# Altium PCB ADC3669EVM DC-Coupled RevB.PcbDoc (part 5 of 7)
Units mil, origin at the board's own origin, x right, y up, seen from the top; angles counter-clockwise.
Board outline 5000 x 2716.54 mil, 12 copper layers (Top Layer, L2 GND, L3 SIG, L4 GND, L5 PWR, L6 GND, L7 GND, L8 PWR, L9 GND, L10 PWR, L11 GND, Bottom Layer), stack 61 mil thick; 546 components, 341 nets, 2088 pads, 1256 vias.
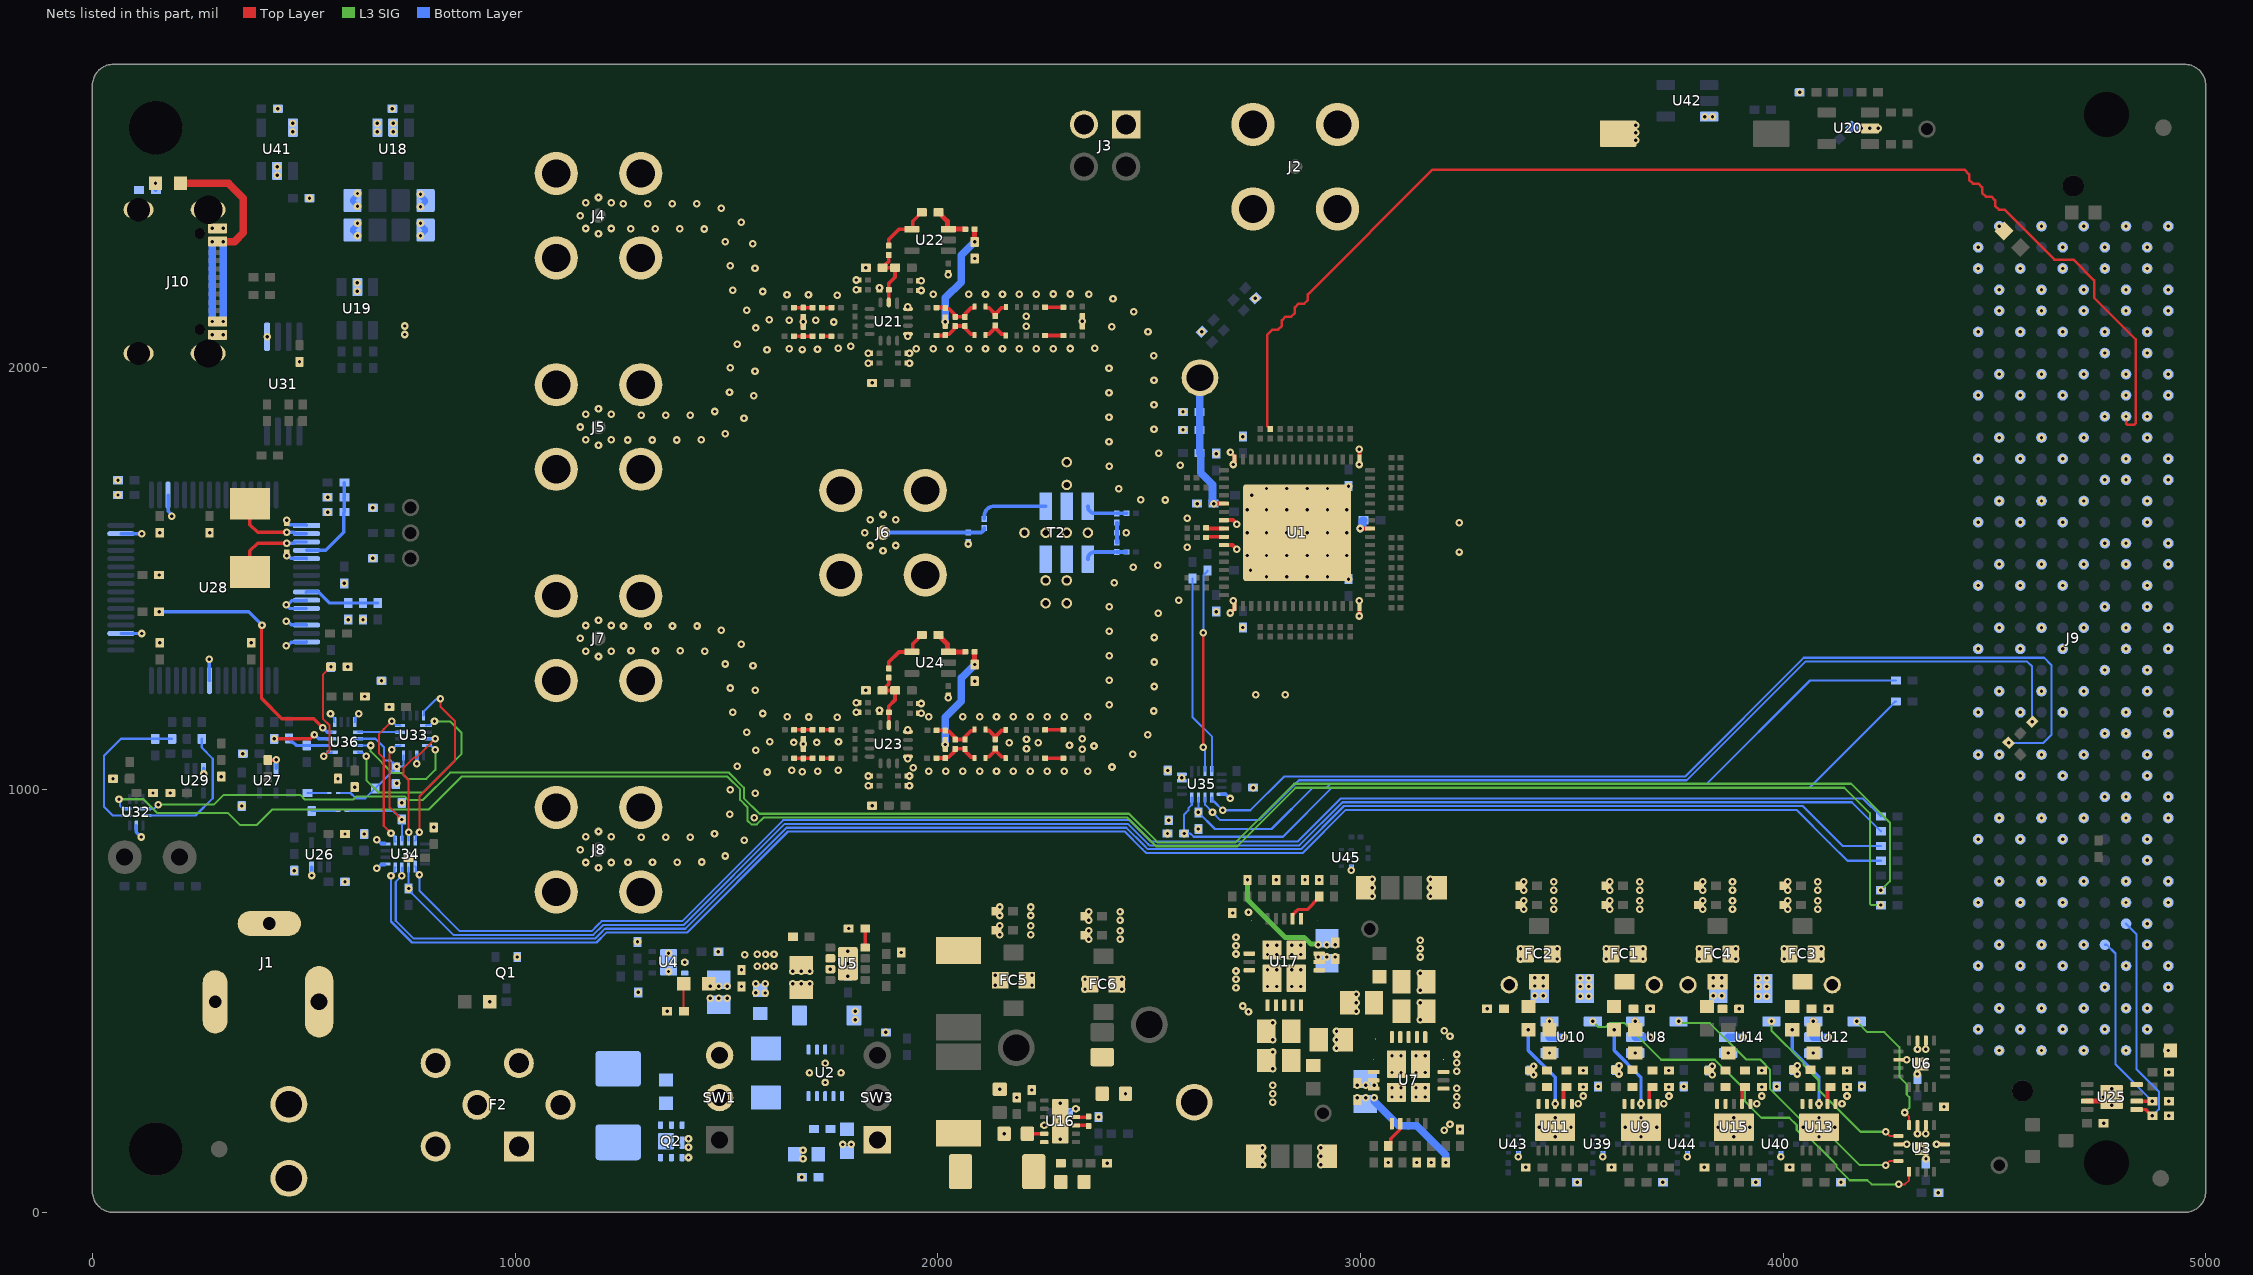
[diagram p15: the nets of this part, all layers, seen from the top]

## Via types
v1: diameter 18, hole 8, Top Layer to Bottom Layer, tented both sides, 1256 vias

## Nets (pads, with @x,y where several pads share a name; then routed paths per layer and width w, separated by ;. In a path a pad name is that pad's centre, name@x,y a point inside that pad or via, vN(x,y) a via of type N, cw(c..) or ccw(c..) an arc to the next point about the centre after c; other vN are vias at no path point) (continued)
FMC_DOUT15_p: J9.C10 R119.2 | length 2919.6
  Top Layer w6: R119.2@2786.79,1853.55 2786.79,1854.33 2783.49,1857.63 2782.96,1857.63 2779.45,1861.15 2779.45,2075.63 2792.38,2088.56 2805.55,2088.56 2814.35,2097.36 2814.35,2110.54 2823.15,2119.34 2836.33,2119.34 2845.13,2128.14 2845.13,2141.31 2853.93,2150.11 2867.1,2150.11 2875.9,2158.92 2875.9,2172.09 3170.82,2467 4429,2467 4440.08,2455.92 4440.08,2442.74 4448.89,2433.94 4462.06,2433.94 4470.86,2425.14 4470.86,2411.97 4479.66,2403.16 4492.84,2403.16 4501.64,2394.36 4501.64,2381.19 4510.44,2372.39 4523.61,2372.39 4641.93,2254.07 4686.72,2254.07 4735.87,2204.92 4735.87,2164.1 4834,2065.97 4834,1866.78 4830.49,1863.27 4814.93,1863.27 4811.42,1866.78 v1(4811.42,1883.27)
FMC_I2C_SCL: R180.1 U32.1 | length 4527.1
  L3 SIG w5: v1(155.65,964.87) 287.52,964.87 310.51,987.86 491.7,987.86 502.7,976.86 616.93,976.86 624.5,984.43 738.73,984.43 747.49,975.68 781.68,975.68 846.47,1040.46 1506.18,1040.46 1541.45,1005.19 1541.45,980.28 1578.32,943.41 2452.43,943.41 2520.3,875.54 2704.8,875.54 2843.47,1014.21 4161.02,1014.21 4252.68,922.54 4252.68,783.37 v1(4231.31,762)
  Bottom Layer w5: U32.1@125.65,954.87 145.65,954.87 v1(155.65,964.87) ; R180.1@4230.91,761.6 v1(4231.31,762)
FMC_I2C_SDA: R181.1 U32.7 | length 4688.5
  L3 SIG w5: v1(62.99,977.49) 121.12,977.49 153.93,944.68 321.2,944.68 349.59,916.29 388.18,916.29 425.33,953.43 795.71,953.43 873.73,1031.46 1502.45,1031.46 1532.45,1001.47 1532.45,976.55 1550.06,958.94 1550.06,927.13 1559.14,918.06 1571.98,918.06 1588.33,934.41 2448.7,934.41 2516.57,866.54 2708.53,866.54 2846.75,1004.76 4145.04,1004.76 4205.43,944.37 4205.43,730.47 4208.35,727.54 v1(4230.78,727.54)
  Bottom Layer w5: v1(62.99,977.49) 65.48,975 65.48,961.9 72.5,954.87 U32.7@80.38,954.87 ; v1(4230.78,727.54) R181.1@4231.31,727
FMC_RESET: R193.1 U34.4 | length 3899.5
  Bottom Layer w5: U34.4@716.56,816.57 715.13,815.13 715.13,806 706.56,797.44 v1(706.56,796.57) 706.56,688.51 756.35,638.73 1192.73,638.73 1216.14,662.14 1406.69,662.14 1645.82,901.27 2442.44,901.27 2484.21,859.49 2493.21,850.49 2863.47,850.49 2965.49,952.51 4031.86,952.51 4110.56,873.81 ; 4110.58,873.81 4152.39,832 R193.1@4231.31,832
FMC_RESET_1p8V: U33.12 U34.9 | length 337.3
  Top Layer w5: v1(706.56,897.59) 689.47,914.69 689.47,1074.79 677.87,1086.39 677.87,1131.63 689.47,1143.22 v1(708.37,1162.13)
  Bottom Layer w5: v1(706.56,897.59) 706.56,896.73 715.13,888.17 715.13,879.03 U34.9@716.56,877.59 ; v1(708.37,1162.13) 709.24,1162.13 717.8,1153.56 726.94,1153.56 U33.12@728.37,1152.13
FMC_SCLK: R200.1 U34.1 | length 3748.3
  Bottom Layer w5: U34.1@763.81,818.54 765.24,817.1 765.24,807.97 773.81,799.41 v1(773.81,798.54) 773.81,760.92 869,665.73 1181.54,665.73 1195.95,680.14 1204.96,689.14 1395.5,689.14 1634.63,928.27 2453.62,928.27 2504.4,877.49 2851.87,877.49 2953.89,979.51 4188.8,979.51 R200.1@4231.31,937
FMC_SCLK_1p8V: U33.16 U34.12 | length 451.4
  Top Layer w5: v1(773.81,899.56) 773.81,984.42 858,1068.61 858,1162 823.49,1196.51 v1(823.49,1215.75)
  Bottom Layer w5: U34.12@763.81,879.56 765.24,881 765.24,890.13 773.81,898.7 v1(773.81,899.56) ; U33.16@783.49,1175.75 784.93,1177.18 784.93,1186.32 812.26,1213.65 821.39,1213.65 v1(823.49,1215.75)
FMC_SDI_1p8V: NT2.1 R208.2 | length 55.5
  Bottom Layer w5: R208.2@518.83,949.74 NT2.1@574.33,949.74
FMC_SDIO_1p8V: NT2.2 R259.1 U33.9 U34.10 | length 376
  Top Layer w5: v1(708.37,1094.88) 708.37,1091.36 703.35,1086.34 703.35,958.53 v1(732.31,929.56)
  Bottom Layer w5: NT2.2@609.33,949.74 712.13,949.74 723,938.87 724.97,938.87 732.31,931.53 v1(732.31,929.56) ; v1(708.37,1094.88) 709.24,1094.88 717.8,1103.44 726.94,1103.44 U33.9@728.37,1104.88 ; U34.10@732.31,879.56 R259.1@732.31,919.56
FMC_SDO: R204.1 U34.3 | length 3874.8
  Bottom Layer w5: U34.3@732.31,816.57 v1(732.31,796.57) 717.8,782.06 717.8,690 760.08,647.73 1189,647.73 1203.41,662.14 1212.41,671.14 1402.96,671.14 1642.09,910.27 2446.16,910.27 2487.94,868.49 2496.94,859.49 2859.33,859.49 2961.35,961.51 4046.38,961.51 4140.89,867 R204.1@4231.31,867
FMC_SEN: R196.1 R199.1 U34.2 | length 3771.5
  Bottom Layer w5: v1(748.06,766.57) 755.4,759.23 755.4,755.33 854,656.73 1185.27,656.73 1208.68,680.14 1399.23,680.14 1638.36,919.27 2449.89,919.27 2498.05,871.12 2500.67,868.49 2855.6,868.49 2957.62,970.51 4162.8,970.51 R199.1@4231.31,902 ; R196.1@748.06,776.57 U34.2@748.06,816.57
FMC_SEN_1p8V: U33.3 U34.11 | length 300.5
  Top Layer w5: v1(748.06,899.56) 748.06,1023.28 736.5,1034.84 736.5,1051.93 761.32,1076.76 767.5,1076.76 v1(811.37,1120.63)
  Bottom Layer w5: U34.11@748.06,879.56 v1(748.06,899.56) ; U33.3@791.37,1120.63 v1(811.37,1120.63)
FTDI_I2C_SCL: R218.2 U32.2 | length 325.5
  Bottom Layer w5: U32.2@127.62,939.13 243.87,939.13 284.7,979.95 284.7,1073.84 258.64,1099.89 R218.2@258.64,1120.63
FTDI_I2C_SDA: R220.2 R221.2 U32.6 | length 360
  Bottom Layer w5: U32.6@80.38,939.13 47.96,939.13 27.5,959.59 27.5,1080.5 67.63,1120.63 R221.2@148.64,1120.63 R220.2@188.64,1120.63
FTDI_RESET: R222.2 U36.4 | length 628.5
  Top Layer w8: v1(401.42,1389.39) 400.19,1388.16 400.19,1216 448.38,1167.81 523.95,1167.81 v1(545.38,1146.38)
  Bottom Layer w8: v1(158.14,1421.08) 369.74,1421.08 v1(401.42,1389.39) ; v1(545.38,1146.38) 555.38,1136.38 U36.4@565.38,1136.38
FTDI_RESET_1p8V: U33.11 U36.9 | length 100
  Bottom Layer w5: U36.9@628.37,1136.38 U33.11@728.37,1136.38
FTDI_SCLK: R212.2 R216.2 U36.1 | length 255.9
  Top Layer w5: v1(547.35,1079.13) 560.88,1092.67 560.88,1152.8 545.38,1168.3 545.38,1271.92 v1(564.43,1290.97)
  Bottom Layer w5: v1(547.35,1079.13) 548.22,1079.13 556.78,1087.7 565.91,1087.7 U36.1@567.35,1089.13
FTDI_SCLK_1p8V: U33.1 U36.12 | length 504.8
  L3 SIG w5: v1(648.37,1079.13) 648.37,1022.59 677.39,993.57 781.67,993.57 873.73,1085.63 873.73,1134.26 846.47,1161.53 810,1161.53 v1(809.4,1162.13)
  Bottom Layer w5: U36.12@628.37,1089.13 629.81,1087.7 638.95,1087.7 647.51,1079.13 v1(648.37,1079.13) ; U33.1@789.4,1152.13 790.84,1153.56 799.97,1153.56 808.53,1162.13 v1(809.4,1162.13)
FTDI_SDI_1p8V: NT1.1 R211.2 | length 44.5
  Bottom Layer w5: R211.2@509.12,992.36 NT1.1@553.66,992.36
FTDI_SDIO_1p8V: NT1.2 R188.2 R266.1 U33.8 U36.10 | length 345.7
  Bottom Layer w5: NT1.2@588.66,992.36 610.64,992.36 623.05,979.95 645.97,979.95 711.7,1045.69 712.66,1045.69 720,1053.03 720,1056.97 712.66,1064.31 710.69,1064.31 706.11,1068.89 692.93,1068.89 690,1071.82 690,1100.46 669.83,1120.63 U36.10@628.37,1120.63 ; R266.1@720,1055.54 733.32,1055.54 736.25,1058.47 U33.8@736.25,1081.26
  other v1: 720,1055
FTDI_SDO: R214.2 U36.3 | length 143.3
  Top Layer w8: v1(430.38,1120.63) 515.38,1120.63 v1(525.38,1130.63)
  Bottom Layer w8: v1(525.38,1130.63) 535.38,1120.63 U36.3@565.38,1120.63
FTDI_SEN: R209.1 R213.2 U36.2 | length 108.1
  Bottom Layer w8: R213.2@465.38,1121.61 465.38,1119.65 471.22,1113.8 473.19,1113.8 482.11,1104.88 U36.2@565.38,1104.88
FTDI_SEN_1p8V: U33.4 U36.11 | length 304.6
  L3 SIG w5: v1(658.37,1104.88) 658.37,1091.05 709.93,1039.5 731.84,1039.5 745.58,1025.76 789.91,1025.76 811.37,1047.21 v1(811.37,1094.88)
  Bottom Layer w5: U36.11@628.37,1104.88 v1(658.37,1104.88) ; U33.4@791.37,1104.88 792.8,1103.44 801.94,1103.44 810.5,1094.88 v1(811.37,1094.88)
GA0_FMC: J9.C34 R185.2 U25.1 | length 537.6
  Top Layer w8: U25.1@4836.47,243.61 4858.47,243.61 4865.66,236.42 4865.66,234.45 4871.5,228.61 v1(4873.47,228.61)
  Bottom Layer w5: J9.C34@4811.42,683.27 4836.12,658.56 4836.12,338.89 4888.97,286.04 4888.97,244.11 v1(4873.47,228.61)
GA1_FMC: J9.D35 R186.2 U25.2 | length 455.8
  Top Layer w8: U25.2@4836.47,263.3 v1(4873.47,263.3)
  Bottom Layer w5: J9.D35@4761.42,633.27 4765.59,633.27 4786.34,612.52 4786.34,350.43 v1(4873.47,263.3)
GND: C1.1 C3.1 C4.1 C5.1 C6.1 C7.1 C8.1 C9.1 C10.1 C11.1 C12.1 C13.1 C14.1 C15.1 C16.1 C17.1 C18.1 C19.1 C20.1 C21.1 C22.1 C23.1 C24.1 C25.1 C26.1 C27.1 C28.1 C29.1 C30.1 C31.1 C32.1 C33.1 C34.1 C35.1 C36.1 C37.1 C38.1 C39.1 C40.1 C41.1 C42.1 C43.1 C44.1 C45.1 C46.1 C47.1 C48.1 C49.1 C50.1 C51.1 C53.1 C54.1 C55.1 C56.1 C57.1 C58.1 C59.1 C60.1 C61.1 C62.1 C63.1 C64.1 C65.1 C66.1 C67.1 C71.1 C72.1 C77.1 C78.1 C80.1 C81.1 C82.1 C83.1 C84.1 C85.1 C86.1 C87.1 C88.1 C89.1 C90.1 C96.1 C99.2 C109.1 C115.1 C118.2 C122.1 C123.1 C124.1 C126.1 C127.1 C128.1 C129.1 C130.1 C131.1 C132.1 C133.1 C135.1 C138.2 C140.1 C142.2 C144.1 C145.1 C146.1 C147.1 C148.1 C149.1 C150.1 C151.1 C152.1 C154.1 C157.2 C159.2 C161.2 C163.1 C164.1 C165.1 C166.1 C167.1 C168.1 C169.1 C170.1 C171.1 C172.1 C173.1 C174.1 C175.1 C176.1 C177.1 C178.1 C180.1 C181.1 C182.1 C183.1 C184.1 C185.1 C186.2 C187.2 C188.2 C189.1 C190.2 D4.2 FC1.2 FC2.2 FC3.2 FC4.2 FC5.2 FC6.2 J2.2 J2.3 J2.4 J2.5 J3.1 J3.3 J4.2 J4.3 J4.4 J4.5 J5.2 J5.3 J5.4 J5.5 J6.2 J6.3 J6.4 J6.5 J7.2 J7.3 J7.4 J7.5 J8.2 J8.3 J8.4 J8.5 J9.A1 J9.A4 J9.A5 J9.A8 J9.A9 J9.A12 J9.A13 J9.A16 J9.A17 J9.A20 J9.A21 J9.A24 J9.A25 J9.A28 J9.A29 J9.A32 J9.A33 J9.A36 J9.A37 J9.A40 J9.B2 J9.B3 J9.B6 J9.B7 J9.B10 J9.B11 J9.B14 J9.B15 J9.B18 J9.B19 J9.B22 J9.B23 J9.B26 J9.B27 J9.B30 J9.B31 J9.B34 J9.B35 J9.B38 J9.B39 J9.C1 J9.C4 J9.C5 J9.C8 J9.C9 J9.C12 J9.C13 J9.C16 J9.C17 J9.C20 J9.C21 J9.C24 J9.C25 J9.C28 J9.C29 J9.C32 J9.C33 J9.C36 J9.C38 J9.C40 J9.D2 J9.D3 J9.D6 J9.D7 J9.D10 J9.D13 J9.D16 J9.D19 J9.D22 J9.D25 J9.D28 J9.D37 J9.D39 J9.E1 J9.E4 J9.E5 J9.E8 J9.E11 J9.E14 J9.E17 J9.E20 J9.E23 J9.E26 J9.E29 J9.E32 J9.E35 J9.E38 J9.E40 J9.F2 J9.F3 J9.F6 J9.F9 J9.F12 J9.F15 J9.F18 J9.F21 J9.F24 J9.F27 J9.F30 J9.F33 J9.F36 J9.F39 J9.G1 J9.G4 J9.G5 J9.G8 J9.G11 J9.G14 J9.G17 J9.G20 J9.G23 J9.G26 J9.G29 J9.G32 J9.G35 J9.G38 J9.G40 J9.H3 J9.H6 J9.H9 J9.H12 J9.H15 J9.H18 J9.H21 J9.H24 J9.H27 J9.H30 J9.H33 J9.H36 J9.H39 J9.J1 J9.J4 J9.J5 J9.J8 J9.J11 J9.J14 J9.J17 J9.J20 J9.J23 J9.J26 J9.J29 J9.J32 J9.J35 J9.J38 J9.J40 J9.K2 J9.K3 J9.K6 J9.K9 J9.K12 J9.K15 J9.K18 J9.K21 J9.K24 J9.K26 J9.K30 J9.K33 J9.K36 J9.K39 J10.1 J10.2 J10.3 J10.4 J10.A1 J10.B1 Q1.2 Q2.4 Q2.7 R3.1 R4.1 R5.1 R11.1 R12.1 R15.1 R17.1 R18.1 R24.1 R26.1 R27.1 R33.1 R34.1 R35.1 R41.1 R43.1 R44.1 R50.1 R51.1 R52.1 R56.1 R57.1 R58.1 R67.1 R69.1 R70.1 R75.1 R78.1 R80.1 R122.2 R123.2 R134.1 R144.1 R146.1 R152.1 R157.1 R163.1 R165.2 R171.1 R176.1 R179.1 R182.1 R185.1 R186.1 R187.1 R190.1 R192.1 R207.1 R210.1 R216.1 R225.1 R240.1 R248.1 R251.1 R252.1 R253.1 R256.1 R259.2 R260.1 R261.1 R262.1 R263.1 R266.2 R267.1 SW2.2 SW3.3 T2.1 T2.2 T2.5 TP2.1 U1.1 U1.16 U1.23 U1.26 U1.33 U1.48 U1.57 U1.65@2732.56,1554.33 U1.65@2732.56,1608.27 U1.65@2732.56,1662.21 U1.65@2777.95,1503.78 U1.65@2777.95,1554.33 U1.65@2777.95,1608.27 U1.65@2777.95,1662.21 U1.65@2777.95,1712.76 U1.65@2825.99,1503.78 U1.65@2825.99,1554.33 U1.65@2825.99,1608.27 U1.65@2825.99,1662.21 U1.65@2825.99,1712.76 U1.65@2850,1608.27 U1.65@2874.02,1503.78 U1.65@2874.02,1554.33 U1.65@2874.02,1608.27 U1.65@2874.02,1662.21 U1.65@2874.02,1712.76 U1.65@2922.05,1503.78 U1.65@2922.05,1554.33 U1.65@2922.05,1608.27 U1.65@2922.05,1662.21 U1.65@2922.05,1712.76 U1.65@2967.44,1554.33 U1.65@2967.44,1608.27 U1.65@2967.44,1662.21 U2.11 U3.2 U3.3 U3.6 U3.15 U3.17 U4.5 U4.7@1363.17,569.93 U4.7@1363.17,591.58 U4.7@1363.17,613.23 U5.3 U5.9 U6.2 U6.3 U6.6 U6.17 U7.1 U7.2 U7.3 U7.5 U7.6 U7.7 U7.8 U7.9 U7.16 U7.17 U7.20 U7.25 U7.26 U7.28 U8.2 U9.6 U9.11 U10.2 U11.6 U11.11 U12.2 U13.6 U13.11 U14.2 U15.6 U15.11 U16.4 U16.13 U17.1 U17.2 U17.3 U17.5 U17.6 U17.7 U17.8 U17.9 U17.16 U17.17 U17.20 U17.25 U17.26 U17.28 U18.2 U19.2 U20.2 U21.11 U21.14 U23.11 U23.14 U25.4 U25.7 U25.9 U26.3 U27.3 U28.1 U28.5 U28.10 U28.11 U28.13 U28.15 U28.25 U28.35 U28.47 U28.51 U29.3 U31.5 U32.4 U33.6 U34.5 U34.8 U35.8 U35.15 U35.16 U36.5 U36.8 U39.3 U40.3 U41.2 U42.3 U43.3 U44.3 U45.3 | length 1746.8
  Top Layer w8: C173.1@415.07,1070 415.38,1070.31 434.44,1070.31 v1(434.75,1070.63) ; U3.6@4272.68,161.29 v1(4292.68,161.29) ; U6.6@4272.68,361.29 v1(4292.69,361.28) ; v1(4317.96,386.56) U6.3@4317.96,406.56 ; v1(4337.64,186.56) U3.2@4337.64,206.56 ; v1(4337.65,386.56) U6.2@4337.64,406.56 ; v1(4362.92,161.29) U3.15@4382.92,161.29
  Top Layer w9.5: U1.26@2670.95,1578.83 U1.26@2676.86,1578.83 ; U1.26@2676.6,1578.57 U1.26@2676.77,1578.74 U1.26@2676.86,1578.83 ; U1.23@2683.19,1637.8 2698.03,1637.8 v1(2707.84,1628.05) v1(2707.84,1628.05) ; 2688.67,1578.83 U1.26@2682.76,1578.83 ; v1(2692.36,1418.14) 2702.19,1427.96 2702.19,1434.87 U1.33@2702.36,1435.04 U1.33@2702.36,1446.85 ; v1(2692.53,1798.23) 2702.36,1788.4 U1.16@2702.36,1781.5 2702.53,1781.33 v1@2702.53,1769.52 ; v1(2707.67,1568.83) 2707.6,1568.83 2697.85,1578.57 2683.02,1578.57 U1.26@2682.76,1578.83 ; v1(2997.64,1411.23) U1.48@2997.64,1435.04 v1(2997.64,1446.85) ; v1(2997.64,1769.69) U1.1@2997.64,1781.5 v1(2997.64,1805.31) ; v1(2999.42,1618.11) U1.57@3023.23,1618.11 ; U1.26@2676.86,1578.83 U1.26@2682.76,1578.83
  Top Layer w12: R144.1@1681.83,2095.24 R146.1@1681.83,2118.54 ; R163.1@1682.22,1096.62 R165.2@1682.22,1119.92 ; v1(1807.52,1183.12) C151.1@1812.52,1183.12 ; v1(1807.52,1206.12) C149.1@1812.52,1206.12 ; v1(1807.52,2183.12) C131.1@1812.52,2183.12 ; v1(1807.52,2206.12) C133.1@1812.52,2206.12 ; v1(1835.35,1009.56) C152.1@1840.35,1009.56 ; v1(1835.35,1032.56) C150.1@1840.35,1032.56 ; v1(1835.35,2009.56) C130.1@1840.35,2009.56 ; v1(1835.35,2032.56) C132.1@1840.35,2032.56 ; C159.2@1862.2,1183.12 v1(1862.2,1188.12) ; C140.1@1862.2,2183.12 v1(1862.2,2188.12) ; C148.1@1928.15,1009.56 v1(1933.15,1009.56) ; C145.1@1928.15,1032.56 v1(1933.15,1032.56) ; C128.1@1928.15,2009.56 v1(1933.15,2009.56) ; C127.1@1928.15,2032.56 v1(1933.15,2032.56) ; v1(1929.53,1073.31) U23.11@1929.53,1078.31 ; U23.14@1929.53,1137.37 v1(1929.53,1142.37) ; v1(1929.53,2073.31) U21.11@1929.53,2078.31 ; U21.14@1929.53,2137.37 v1(1929.53,2142.37) ; C146.1@1955.98,1181.15 v1(1960.98,1181.15) ; C147.1@1955.98,1204.15 v1(1960.98,1204.15) ; C126.1@1955.98,2181.15 v1(1960.98,2181.15) ; C129.1@1955.98,2204.15 v1(1960.98,2204.15) ; v1(2025.23,1218.07) C163.1@2025.23,1223.07 ; v1(2025.23,2218.07) C144.1@2025.23,2223.07 ; U25.7@4719.22,263.3 4777.42,263.3 U25.9@4777.42,273.14
  Bottom Layer w5: v1(563.26,1180) 563.26,1179.13 571.82,1170.57 571.82,1161.44 U36.5@573.26,1160 ; U36.8@620.5,1160 621.94,1161.44 621.94,1170.57 630.5,1179.13 v1(630.5,1180)
  Bottom Layer w8: U28.35@67.63,1369.71 v1(116.5,1369.71) ; U28.47@67.63,1605.93 v1(116.8,1605.93) ; U32.4@104,915.5 104,899.99 v1(115.82,888.17) ; U28.51@178.85,1697.47 179.58,1696.74 179.58,1658.51 187.91,1650.17 v1(187.91,1647.47) ; U29.3@263.01,1050.63 263.42,1050.22 v1(263.42,1037.44) ; v1(276.64,1308.49) 276.96,1308.17 276.96,1258.8 U28.25@277.27,1258.49 ; U27.3@434.75,1050.63 v1(434.75,1070.63) ; v1(459.06,1340.52) 461.77,1340.52 469.11,1347.86 ; v1(459.06,1398.9) 461.77,1398.9 469.11,1391.56 ; v1(459.45,1638.06) 459.45,1635.36 466.05,1628.76 466.05,1627.03 505.19,1627.03 U28.1@506.6,1625.62 ; v1(459.92,1554.11) 462.63,1554.11 469.14,1547.6 505.87,1547.6 U28.5@506.6,1546.88 ; 469.14,1347.86 470.57,1349.3 505.87,1349.3 U28.15@506.6,1350.02 ; 469.14,1391.56 470.57,1390.12 505.87,1390.12 U28.13@506.6,1389.39 ; U28.11@506.6,1428.77 468.46,1428.77 v1(459.06,1438.17) 461.77,1438.17 471.32,1447.72 505.87,1447.72 U28.10@506.6,1448.45 ; v1(518.83,797.1) U26.3@518.83,817.1 ; v1(672.94,814.44) 673.81,814.44 682.37,823.01 U34.5@691.5,823.01 ; v1(672.94,881.69) 673.81,881.69 682.37,873.13 U34.8@691.5,873.13 ; v1(767.74,1061.26) U33.6@767.74,1081.26 ; U35.8@2671.9,989.51 2681.9,989.51 v1(2691.9,979.51) ; v1(2978.59,809.7) U45.3@2978.59,819.7 ; v1(3373.64,131.6) U43.3@3373.64,141.6 ; v1(3573.64,131.6) U39.3@3573.64,141.6 ; v1(3773.64,131.6) U44.3@3773.64,141.6 ; v1(3994.95,131.6) U40.3@3994.95,141.6
  Bottom Layer w12: v1(627.29,2310.67) 615.29,2322.67 615.29,2325.67 627.29,2337.67 v1(627.29,2340.67) ; v1(627.29,2380.67) 615.29,2392.67 615.29,2395.67 627.29,2407.67 v1(627.29,2410.67) ; v1(776.4,2310.67) 788.4,2322.67 788.4,2325.67 776.4,2337.67 v1(776.4,2340.67) ; v1(776.4,2379.17) 788.4,2391.17 C67.1@788.4,2394.17 776.4,2406.17 v1(776.4,2409.17)
  Bottom Layer w18: v1(2999.42,1618.11) 3004.86,1623.55 3004.86,1636.95 3005.7,1637.8 C89.1@3007.67,1637.8 ; U10.2@3447.46,414.63 v1(3482.46,414.63) ; U8.2@3650.39,414.63 v1(3685.39,414.63) ; U14.2@3870.14,414.63 v1(3905.14,414.63) ; U12.2@4071.7,414.63 v1(4106.7,414.63) ; C90.1@4161.27,2567.84 4162.66,2569.23 4163.85,2569.23 4165.24,2567.84 4182.64,2567.84 v1(4185.47,2565)
  other v1: 4367.17,46.52 3512.81,71.52 3715.74,71.52 3935.5,71.52 4137.05,71.52 1678.63,83 3391.19,106.52 3594.12,106.52 3813.87,106.52 4015.43,106.52 2768.31,112.92 2905.79,112.92 2400.89,116.54 3065.64,118.06 3133.64,118.06 3167.64,118.06 1681.27,127.4 4338.16,127.51 1410.41,130.01 2768.31,132.92 2905.79,132.92 1681.27,147.4 2768.31,152.92 2905.79,152.92 1410.41,154.65 1775.71,160.92 1795.71,160.92 1410.41,174.65 2157.03,186.23 4317.96,186.56 3198.26,194.89 3235.64,196.8 2252.15,205.91 3211.98,208.61 4758.59,211.18 2380.54,225.88 4912.84,228.61 4380.59,250.04 3228.02,253.79 3515.17,256.76 3718.1,256.76 3937.86,256.76 4139.41,256.76 2792.37,260.81 4912.84,263.3 2187.15,271.86 3228.02,273.79 3527.06,275.54 3729.98,275.54 3949.74,275.54 4151.29,275.54 2444.25,280.81 2792.37,280.81 2222.15,289.65 2146.65,291.54 3228.02,293.79 3526.98,296.76 3729.91,296.76 3949.67,296.76 4151.22,296.76 3562.31,298.12 3765.24,298.12 3985,298.12 4186.55,298.12 2792.37,300.81 2992.94,300.72 3012.94,300.72 3032.94,300.72 3409.66,325.73 3832.35,325.73 3611.77,327.49 4033.08,327.49 4317.49,327.5 4912.84,331.98 3228.02,333.79 3526.98,335.73 3729.91,335.73 3949.67,335.73 4151.22,335.73 2792.37,339.55 3409.66,345.73 3832.35,345.73 3611.77,347.49 4033.08,347.49 3228.02,353.79 3228.02,373.79 2792.37,379.55 4511.42,383.27 4611.42,383.27 4711.42,383.27 4811.42,383.27 4911.42,383.27 2943.43,388.86 2792.37,408.86 2943.43,408.86 3211.98,416.61 1877.26,425.96 2943.43,428.86 3198.26,430.33 4461.42,433.27 4561.42,433.27 4661.42,433.27 4761.42,433.27 4861.42,433.27 2792.37,448.86 1805.21,456.17 3141.27,456.31 2735.38,474.85 1360,476.33 1805.21,476.17 2990.21,476.31 3300.05,481.63 3685.56,481.66 3896.12,481.6 4107.02,481.63 4511.42,483.27 4611.42,483.27 4711.42,483.27 4811.42,483.27 4861.42,483.27 2721.66,488.57 2990.21,496.31 3141.27,496.31 1461.94,506.44 1481.94,506.44 1501.94,506.44 2990.21,516.31 1291.77,520.71 3141.27,525.62 2348.51,528.1 2435.5,528.1 2705.62,531.39 4761.42,533.27 4911.42,533.27 1535.7,534.5 1656.98,541.25 1676.98,541.25 1696.98,541.25 2705.62,551.39 2348.51,552.1 2435.5,552.1 3141.27,565.62 2705.62,571.39 1745.84,575.52 4461.42,583.27 4561.42,583.27 4661.42,583.27 4811.42,583.27 4911.42,583.27 1401.56,591.58 3378.76,599.64 3465.76,599.64 3581.69,599.64 3668.69,599.64 3801.45,599.64 3888.44,599.64 4003,599.64 4089.99,599.64 1005.06,604.5 2900.69,604.45 2920.69,604.45 2940.69,604.45 3141.27,604.36 2705.62,611.39 1913.52,614.89 3378.76,623.64 3465.76,623.64 3581.69,623.64 3668.69,623.64 3801.45,623.64 3888.44,623.64 4003,623.64 4089.99,623.64 3141.27,624.36 2705.62,631.39 4511.42,633.27 4611.42,633.27 4711.42,633.27 4861.42,633.27 1289.77,640.41 3141.27,644.36 2357.63,646.04 2431.37,646.04 2705.62,651.39 2146.41,656.65 2220.15,656.65 2357.63,666.04 2431.37,666.04 1789.15,671.71 2146.41,678.65 2220.15,678.65 4861.42,683.27 2357.63,691.04 2431.37,691.04 2146.41,702.65 2220.15,702.65 2698,708.37 2735.38,710.28 2357.63,711.04 2431.37,711.04 3386.83,717.59 3457.69,717.59 3589.76,717.59 3660.62,717.59 3809.51,717.59 3880.38,717.59 4011.07,717.59 4081.93,717.59 2146.41,722.65 2220.15,722.65 4461.42,733.27 4561.42,733.27 4661.42,733.27 4811.42,733.27 4911.42,733.27 3386.83,737.59 3457.69,737.59 3589.76,737.59 3660.62,737.59 3809.51,737.59 3880.38,737.59 4011.07,737.59 4081.93,737.59 3028.23,748 3165.71,748 3386.83,762.59 3457.69,762.59 3589.76,762.59 3660.62,762.59 3809.51,762.59 3880.38,762.59 4011.07,762.59 4081.93,762.59 3028.23,768 3165.71,768 597.57,782.1 3386.83,782.59 3457.69,782.59 3589.76,782.59 3660.62,782.59 3809.51,782.59 3880.38,782.59 4011.07,782.59 4081.93,782.59 4511.42,783.27 4611.42,783.27 4711.42,783.27 4811.42,783.27 4911.42,783.27 2801,787.11 2869,787.11 2903,787.11 3028.23,788 3165.71,788 477.93,808.7 1197.5,815.27 1167.09,827.86 1227.91,827.86 1267.31,828.93 1325.31,828.93 1383.31,828.93 1441.31,829.09 4861.42,833.27 1497.52,843.38 748.06,844.13 1154.5,858.27 1542.06,880.53 4461.42,883.27 4561.42,883.27 4661.42,883.27 4861.42,883.27 1298.53,887.61 1356.53,887.61 1414.53,887.61 1167.09,888.68 1227.91,888.68 597.57,895.37 642.94,895.31 1471.92,895.97 2543.66,896.64 1197.5,901.27 2616.78,907.27 807.43,911.06 2546.55,927.91 1565.56,933.56 4511.42,933.27 4611.42,933.27 4711.42,933.27 4811.42,933.27 4911.42,933.27 1507.55,941.74 353.29,961.74 1844.88,962.56 732.31,968.93 4761.42,983.27 4811.42,983.27 4911.42,983.27 1568.2,991.49 143.37,992.5 184.27,992.36 1509.52,999.71 2746.27,1005.26 620.5,1006.14 720,1015.63 48.88,1026.14 581.13,1026.14 2577.41,1028.88 304.91,1031.11 4561.42,1033.27 4661.42,1033.27 4861.42,1033.27 1596.59,1042.07 1679.92,1042.91 1716.26,1043.41 2355.19,1043.52 1979.13,1043.91 2019.13,1043.91 2059.13,1043.91 2099.13,1043.91 2139.13,1043.91 2179.13,1043.91 2219.13,1043.91 2259.13,1043.91 2299.13,1043.91 2544.26,1045.62 1654.45,1046.04 1764.91,1046.23 1942.37,1052.3 2412.24,1053.94 1525.58,1055.44 4461.42,1083.27 4511.42,1083.27 4611.42,1083.27 4711.42,1083.27 4861.42,1083.27 2461.85,1083.99 356.01,1085.63 1569.09,1093.78 2342.1,1095.77 2210,1096.65 2369.82,1103.69 2311.85,1105.46 1682.22,1108.27 2169.66,1111.3 2238.13,1111 1659,1112 1714,1112 1602.2,1113.59 1765.31,1113.44 2210,1119.89 2342.09,1120.77 2496.81,1130.27 4761.42,1133.27 4811.42,1133.27 4911.42,1133.27 1548.58,1135.71 1762.31,1171.36 1643.71,1172.84 1694.71,1172.15 1979.13,1172.49 2059.13,1172.49 2099.13,1172.49 2139.13,1172.49 2179.13,1172.49 2219.13,1172.49 2259.13,1172.49 2299.13,1172.49 2354.79,1173.1 1586.21,1180.43 1515.29,1183.2 4461.42,1183.27 4561.42,1183.27 4661.42,1183.27 4811.42,1183.27 4911.42,1183.27 2511.48,1186.38 702.63,1195.75 2405.66,1200.97 644.56,1220.56 2752.8,1224.77 2821.8,1224.77 4511.42,1233.27 4611.42,1233.27 4711.42,1233.27 4861.42,1233.27 1568.2,1235.56 1829.88,1235.12 1509.52,1240.91 2512.19,1244.38 684.09,1257.76 2087.28,1256.93 2405.66,1258.97 4761.42,1283.27 4861.42,1283.27 603.8,1290.97 1563.07,1293.33 1497.73,1297.7 2512.19,1302.38 1197.5,1315.27 2405.66,1316.97 1167.09,1327.86 1227.91,1327.86 1448.4,1328.2 1274.4,1328.93 1332.4,1328.93 1390.4,1328.93 4461.42,1333.27 4561.42,1333.27 4661.42,1333.27 4811.42,1333.27 4911.42,1333.27 1535.11,1344.15 159.16,1347.86 375.7,1347.86 1154.5,1358.27 2512.19,1360.38 2405.66,1374.97 1487.74,1377.62 2722.05,1383.86 4511.42,1383.27 4611.42,1383.27 4711.42,1383.27 4811.42,1383.27 4911.42,1383.27 1256.61,1387.61 1314.61,1387.61 1372.61,1387.61 1430.61,1387.61 1167.09,1388.68 1227.91,1388.68 1197.5,1401.27 605.19,1402.59 640.19,1402.59 2521.53,1417.62 2658.96,1421.26 2405.66,1432.97 4761.42,1433.27 4861.42,1433.27 2699.36,1446.85 2570.65,1448.46 4461.42,1483.27 4561.42,1483.27 4661.42,1483.27 4861.42,1483.27 595.94,1488.59 2417.77,1489.69 2971.95,1498.22 158.14,1508.23 2739.95,1519.69 2462.71,1526.35 2520.5,1531.31 4511.42,1533.27 4611.42,1533.27 4711.42,1533.27 4811.42,1533.27 4911.42,1533.27 663.63,1547.55 3233.5,1562.44 1870.59,1565.27 2589.99,1573.71 1840.18,1577.86 1900.99,1577.86 2072.59,1581.49 4761.42,1583.27 4811.42,1583.27 4911.42,1583.27 159.16,1608.1 277.27,1608.1 1827.59,1608.27 2445.88,1608.27 3233.5,1631.44 4461.42,1633.27 4561.42,1633.27 4661.42,1633.27 4861.42,1633.27 1840.18,1638.68 1900.99,1638.68 2589.99,1642.71 1870.59,1651.27 556.57,1657.04 663.63,1667.55 2613.59,1677.17 4511.42,1683.27 4611.42,1683.27 4711.42,1683.27 4861.42,1683.27 2538.16,1685.52 2480.17,1686.43 556.57,1692.04 2742.95,1696.85 60.74,1697.47 2428.27,1712.34 2971.95,1718.32 60.74,1732.47 4761.42,1733.27 4811.42,1733.27 4911.42,1733.27 2405.57,1765.71 2573.37,1768.05 2699.53,1769.52 4461.42,1783.27 4561.42,1783.27 4661.42,1783.27 4811.42,1783.27 4911.42,1783.27 2658.96,1795.28 2522.69,1796.26 1197.5,1815.27 2405.16,1823.71 1167.09,1827.86 1227.91,1827.86 1266.92,1827.55 1324.92,1827.55 1382.92,1827.55 1440.92,1827.72 4511.42,1833.27 4611.42,1833.27 4711.42,1833.27 4861.42,1833.27 2722.05,1835.68 1497.13,1842 2580.32,1851.39 2511.69,1853.21 1154.5,1858.27 1541.67,1879.15 2405.16,1881.71 4761.42,1883.27 4861.42,1883.27 1298.69,1886.23 1356.69,1886.23 1414.69,1886.23 1167.09,1888.68 1227.91,1888.68 1472.04,1894.87 2580.32,1893.97 1197.5,1901.27 2511.69,1911.21 1565.16,1932.18 4461.42,1933.27 4561.42,1933.27 4661.42,1933.27 4811.42,1933.27 4911.42,1933.27 2405.16,1939.71 1507.32,1940.91 1844.88,1962.56 2511.69,1969.21 4511.42,1983.27 4611.42,1983.27 4711.42,1983.27 4811.42,1983.27 4911.42,1983.27 1567.8,1990.12 2405.16,1997.71 1509.12,1998.88 490.07,2012.51 2511.23,2027.2 4761.42,2033.27 4861.42,2033.27 1596.19,2040.69 1679.52,2041.53 1715.43,2042.45 1648.81,2043.03 1949.34,2043.62 1989.34,2043.72 2029.34,2043.83 2073.12,2043.33 2113.12,2043.43 2153.12,2043.54 2193.12,2043.64 2233.12,2043.75 2273.12,2043.85 1764.52,2044.66 2313.12,2043.95 2371.12,2044.67 1793.9,2049.56 1525.47,2054.53 413.3,2071.88 283.46,2076.45 309.46,2076.45 739.45,2077.24 2497.55,2083.57 2624.5,2083.65 4461.42,2083.27 4561.42,2083.27 4661.42,2083.27 4761.42,2083.27 4861.42,2083.27 1569.17,2092.66 2411.52,2095.46 2209.59,2096.77 739.45,2097.24 1754.23,2106.74 1681.83,2106.89 2342.1,2108.56 1648.62,2111.22 1711.37,2111.22 1601.73,2112.21 2209.59,2120 2463.81,2130.74 4511.42,2133.27 4611.42,2133.27 4711.42,2133.27 4811.42,2133.27 4911.42,2133.27 1548.13,2134.37 2414.73,2161.65 2751.61,2162.62 1694.32,2170.77 1761.92,2169.98 1643.4,2171.46 1989.34,2172.72 2073.12,2172.33 2113.12,2172.43 2153.12,2172.54 2193.12,2172.64 2233.12,2172.75 2273.12,2172.85 2357.76,2172.51 2313.12,2172.95 626.85,2179.6 1585.89,2178.99 1514.88,2181.89 4511.42,2183.27 4611.42,2183.27 4711.42,2183.27 4811.42,2183.27 4911.42,2183.27 626.85,2199.6 4461.42,2233.27 4561.42,2233.27 4661.42,2233.27 4761.42,2233.27 4861.42,2233.27 1567.8,2234.1 1829.88,2235.12 1509.12,2239.6 2087.28,2256.93 4461.42,2283.27 4661.42,2283.27 4761.42,2283.27 4861.42,2283.27 1562.7,2291.87 1497.29,2296.38 1197.5,2315.27 1447.92,2326.83 1167.09,2327.86 1227.91,2327.86 1273.93,2327.55 1331.93,2327.55 1389.93,2327.55 283.46,2328.42 309.46,2328.42 4511.42,2333.27 4611.42,2333.27 4711.42,2333.27 4811.42,2333.27 4911.42,2333.27 1534.78,2342.71 1154.5,2358.27 1487.43,2376.21 1256.3,2386.23 1314.3,2386.23 1372.3,2386.23 1430.3,2386.23 1167.09,2388.68 1227.91,2388.68 513.72,2399.8 1197.5,2401.27 436.95,2454.17 436.95,2474.17 3651.89,2536.27 3651.89,2554.3 711.75,2556.54 4205.47,2565 4225.47,2565 3651.89,2572.32 711.75,2576.54 3815,2592.6 3833.03,2592.6 4039.37,2650
GPIO0: R111.2 U35.3 | length 479.9
  Top Layer w5: v1(2628.11,1100.5) v1@2628.11,1371.35
  Bottom Layer w5: v1(2628.11,1100.5) 2632.53,1096.08 U35.3@2632.53,1044.63 ; v1(2628.4,1371.65) 2628.4,1507 2638.33,1516.93 R111.2@2638.33,1518.9
GPIO0_DIR: R194.1 R261.2 U35.11 | length 1846.8
  Bottom Layer w5: U35.11@2616.78,981.64 v1(2616.78,946.64) 2656.15,907.27 2789.6,907.27 2886.84,1004.51 2919.83,1004.51 2928.83,1013.51 3818.48,1013.51 4063.64,1258.67 R194.1@4266.68,1258.67
GPIO0_VADJ: R197.1 U35.10 | length 2279.6
  Bottom Layer w5: U35.10@2632.53,981.64 2632.53,964.26 v1(2650.15,946.64) 2668.49,928.3 2760.42,928.3 2854.63,1022.51 3771.93,1022.51 4052.72,1303.3 4577.47,1303.3 4589.26,1291.51 v1(4589.26,1161.11)
GPIO1: R121.1 U35.4 | length 475
  Bottom Layer w5: R121.1@2602.87,1500 2602.87,1171.51 2649.26,1125.13 2649.26,1045.61 U35.4@2648.28,1044.63
GPIO1_DIR: R195.1 R260.2 U35.12 | length 1912.9
  Bottom Layer w5: U35.12@2601.03,981.64 2601.03,964.64 2592.94,956.55 2592.94,951.5 2583.03,941.59 v1(2583.03,896.64) 2597.72,896.64 2605.4,888.96 2817.01,888.96 2932.56,1004.51 4062.51,1004.51 4257.37,1199.36 4257.37,1201.33 4264.71,1208.67 R195.1@4266.68,1208.67
GPIO1_VADJ: R198.1 U35.9 | length 2434.9
  Bottom Layer w5: U35.9@2648.28,981.64 2648.28,973.77 2649.72,972.33 2653.75,972.33 v1(2674.57,951.5) 2739.65,951.5 2819.65,1031.51 3768.2,1031.51 4048.99,1312.3 4617.75,1312.3 4635.17,1294.88 4635.17,1130.01 4616.27,1111.11 v1(4533.58,1111.11)
ISENSE_AVDD12: U3.9 U10.4 | length 965.6
  Top Layer w5: v1(4273.27,66.33) 4288.27,66.33 4298.27,76.33 U3.9@4298.27,96.33
  L3 SIG w5: v1(3549.82,452.04) 3563.08,438.77 3580.41,438.77 3589.48,447.85 3625.21,447.85 3711.83,361.23 3838.77,361.23 3910.3,289.7 3910.3,262.4 3948.52,224.18 4014.88,224.18 4032.24,206.81 4032.24,195.25 4041.29,186.2 4052.85,186.2 4117.03,122.02 4126.11,112.94 4126.11,107.86 4157.64,76.33 4199.53,76.33 4209.53,66.33 v1(4273.27,66.33)
ISENSE_AVDD18: U3.5 U14.4 | length 441.9
  Top Layer w5: v1(4242.68,190.97) 4252.68,180.97 U3.5@4272.68,180.97
  L3 SIG w5: v1(3972.5,452.04) 3972.5,429.99 4048.58,353.91 4048.58,348.76 4085.08,312.26 4085.08,289.17 4183.28,190.97 v1(4242.68,190.97)
ISENSE_DVDD12: U3.8 U8.4 | length 692
  Top Layer w5: v1(4242.68,111.92) 4252.68,121.92 U3.8@4272.68,121.92
  L3 SIG w5: v1(3752.75,452.04) 3756.27,452.04 3760.45,447.85 3826.56,447.85 3912.68,361.73 3945.59,361.73 3969.5,337.82 3969.5,291.7 4044.12,217.08 4054.07,217.08 4076.71,194.44 4098.45,194.44 4180.98,111.92 v1(4242.68,111.92)
ISENSE_DVDD18: U3.4 U12.4 | length 329.1
  Top Layer w5: v1(4288.27,236.56) 4298.27,226.56 U3.4@4298.27,206.56
  L3 SIG w5: v1(4174.06,452.04) 4199.53,426.56 4239.53,426.56 4275.12,390.97 4275.12,320.75 4292.69,303.18 4292.69,278.83 4298.77,272.75 4298.77,247.76 4288.27,237.26 v1(4288.27,236.56)
MainPwr: C1.2 C7.2 C8.2 C14.2 C15.2 C59.2 C60.2 D1.1 FB1.2 R7.2 R8.2 R14.2 R61.2 R62.2 R65.2 U4.6 U5.2 U7.18 U17.18 U18.1 U41.5 | length 507.6
  L3 SIG w12: v1(2733,787.11) 2733,739.53 2821.66,650.87 2866.9,650.87 2874.05,643.72 2883.12,634.66 2899.54,634.66 v1(2900.69,633.51)
  Bottom Layer w18: v1(3032.94,271.66) 3032.94,263.06 3091.05,204.95 3133.64,204.95 3201.64,136.95 v1(3201.64,118.06)
  other v1: 2992.94,271.35 3012.94,271.66 1569.51,519.39 1591.91,519.27 1461.94,535.5 1481.94,535.5 1501.94,535.5 1569.21,541.49 1591.61,541.37 1656.98,570.31 1676.98,570.31 1696.98,570.31 1535.7,573.87 1572.67,582.17 1592.67,582.17 1612.67,582.17 1543.83,609.31 1572.67,611.33 1592.67,611.33 1612.67,611.33 1480.98,617.12 2920.69,633.51 2940.69,633.51 474.35,2556.54 674.35,2556.54 474.35,2576.54 674.35,2576.54 438.91,2611.54 709.78,2611.54
NetC2_1: C2.1 D3.2 F2.2 Q2.3 SW1.2
NetC2_2: C2.2 D3.1 F2.4 Q2.1 Q2.2 Q2.5 Q2.6 Q2.8
NetC3_2: C3.2 R2.1 R5.2 U2.2
NetC4_2: C4.2 U2.1
NetC13_2: C13.2 U5.8 | length 45
  Top Layer w8: U5.8@1828.52,626.71 C13.2@1828.52,671.71
NetC16_2: C16.2 C17.2 C18.2 FB2.1 U7.10 U7.11 U7.12 U7.13 U7.14 U7.15 U7.27
NetC21_2: C21.2 U7.21 | length 64.7
  Top Layer w8: C21.2@3065.64,157.43 3071.42,163.22 3071.42,174.27 3093.34,196.19 3093.34,209.33 U7.21@3094.26,210.25
NetC24_2: C24.2 R20.2 R21.2 U8.1 U9.9 U9.10
  other v1: 3650.39,377.23
NetC25_2: C25.2 FB3.2 FC1.1 PP3.1 R25.2
  other v1: 3519.99,511.96 3539.99,511.96 3519.99,534.57 3539.99,534.57 3519.99,554.57 3539.99,554.57
NetC28_2: C28.2 R27.2 U9.7 | length 44
  Top Layer w9: U9.7@3683.46,256.76 3683.46,291.42 3688.8,296.76 C28.2@3690.54,296.76
NetC31_2: C31.2 R29.2 R30.2 U10.1 U11.9 U11.10
  other v1: 3447.46,377.23
NetC32_2: C32.2 FB4.2 FC2.1 PP4.1 R25.1
  other v1: 3412.26,513.09 3432.26,513.09 3412.26,535.7 3432.26,535.7 3412.26,555.7 3432.26,555.7
NetC35_2: C35.2 R35.2 U11.7 | length 44
  Top Layer w9: U11.7@3480.53,256.76 3480.53,291.42 3485.87,296.76 C35.2@3487.61,296.76
NetC38_2: C38.2 R37.2 R38.2 U12.1 U13.9 U13.10
  other v1: 4071.7,377.23
NetC39_2: C39.2 FB5.2 FC3.1 PP5.1 R42.2
  other v1: 3941.3,511.96 3961.3,511.96 3941.3,534.57 3961.3,534.57 3941.3,554.57 3961.3,554.57
NetC42_2: C42.2 R44.2 U13.7 | length 44
  Top Layer w9: U13.7@4104.77,256.76 4104.77,291.42 4110.11,296.76 C42.2@4111.85,296.76
NetC45_2: C45.2 R46.2 R47.2 U14.1 U15.9 U15.10
  other v1: 3870.14,377.23
NetC46_2: C46.2 FB6.2 FC4.1 PP6.1 R42.1
  other v1: 3834.94,513.09 3854.94,513.09 3834.94,535.7 3854.94,535.7 3834.94,555.7 3854.94,555.7
NetC49_2: C49.2 R52.2 U15.7 | length 44
  Top Layer w9: U15.7@3903.21,256.76 3903.21,291.42 3908.55,296.76 C49.2@3910.3,296.76
NetC52_1: C52.1 U16.10 | length 30.5
  Top Layer w8: U16.10@2326.95,225.6 2355.77,225.6 C52.1@2356.95,226.78
NetC52_2: C52.2 U16.9 | length 30.5
  Top Layer w8: U16.9@2326.95,205.91 2355.77,205.91 C52.2@2356.95,204.73
NetC53_2: C53.2 D5.1 R53.2 U16.6
NetC54_2: C54.2 U16.5 | length 40
  Top Layer w8: C54.2@2212.15,186.23 U16.5@2252.15,186.23
NetC55_2: C55.2 R55.2 R59.1 U16.11 | length 21.8
  Bottom Layer w5: R55.2@2308.56,237.05 2315.36,243.85 2325.52,243.85 v1(2326.95,245.28)
NetC61_2: C61.2 C62.2 C63.2 FB8.1 U17.10 U17.11 U17.12 U17.13 U17.14 U17.15 U17.27
NetC66_2: C66.2 U17.21 | length 92
  Top Layer w8: U17.21@2839.38,694.92 2839.38,703.78 2846.14,710.55 2846.14,710.87 2851.98,716.7 2873.93,716.7 2903,745.77 C66.2@2903,747.74
NetC92_2: C92.2 R129.1 | length 43
  Top Layer w9: C92.2@2254.05,2141.82 R129.1@2297.05,2141.82
NetC101_1: C101.1 R130.1 | length 43
  Top Layer w9: C101.1@2254.05,2074.72 R130.1@2297.05,2074.72
NetC104_1: C104.1 J6.1 R134.2 | length 245.9
  Bottom Layer w9: v1(1870.59,1608.27) 1870.72,1608.41 2072.45,1608.41 2072.59,1608.27 R134.2@2072.59,1608.54 2099.42,1608.54 ccw(c2099.42,1619.15) C104.1@2110.03,1619.15
NetC104_2: C104.2 T2.6 | length 164.7
  Bottom Layer w9: C104.2@2110.03,1641.2 2110.03,1647.25 cw(c2133.65,1647.25) 2133.65,1670.87 T2.6@2255.23,1670.87
NetC105_1: C105.1 R132.2 T2.4 | length 95.2
  Bottom Layer w9: T2.4@2355.23,1670.87 ccw(c2372,1670.87) 2372,1654.1 R132.2@2417.83,1654.1 ; R132.2@2423.83,1654.1 C105.1@2446.83,1654.1
NetC106_2: C106.2 U1.24 | length 42.3
  Top Layer w9: C106.2@2635.03,1619.53 2635.27,1619.29 2636.45,1618.11 U1.24@2676.77,1618.11
NetC107_2: C107.2 U1.25 | length 82.6
  Top Layer w9: C107.2@2635.03,1597.01 2635.27,1597.25 C107.2@2636.45,1598.43 ; C107.2@2636.45,1598.43 U1.25@2676.77,1598.43 C107.2@2636.45,1598.43
NetC108_1: C108.1 R135.2 T2.3 | length 95.2
  Bottom Layer w9: T2.3@2355.23,1545.67 cw(c2372,1545.67) 2372,1562.44 R135.2@2417.83,1562.44 ; R135.2@2423.83,1562.44 C108.1@2446.83,1562.44
NetC109_2: C109.2 R132.1 R135.1 | length 46
  Bottom Layer w9: R135.1@2423.83,1585.27 C109.2@2423.83,1608.27 R132.1@2423.83,1631.27
NetC111_1: C111.1 R137.1 | length 43
  Top Layer w9: C111.1@2254.05,1141.82 R137.1@2297.05,1141.82
NetC120_2: C120.2 R138.1 | length 43.1
  Top Layer w9: C120.2@2254.05,1074.72 2296.92,1074.72 R138.1@2297.05,1074.85
NetC122_2: C122.2 C123.2 C124.2 R139.1 TP4.1 U1.21 | length 336.9
  Top Layer w9.5: v1(2652.96,1677.17) U1.21@2676.77,1677.17
  Bottom Layer w18: TP4.1@2620.51,1975 2620.1,1974.59 2620.1,1894.38 C123.2@2619.69,1893.97 C122.2@2619.69,1851.39 R139.1@2619.69,1796.62 2621.65,1796.62 2622.5,1795.78 2622.5,1749.69 2650.15,1722.04 2650.15,1679.98 v1(2652.96,1677.17)
NetC134_1: C134.1 R140.2 R144.2 | length 44
  Top Layer w9: R140.2@1659.83,2073.19 R144.2@1681.83,2073.19 C134.1@1703.83,2073.19
NetC134_2: C134.2 R141.1 | length 22.4
  Top Layer w9: C134.2@1725.88,2073.19 R141.1@1748.25,2073.19
NetC136_1: C136.1 L7.1 R145.1 R150.2 R154.2 | length 114.3
  Top Layer w9: R150.2@1997,2074.93 2018.02,2074.93 R154.2@2018.02,2075.71 2019.81,2077.51 2026.25,2077.51 2039.41,2090.68 2039.41,2094.9 C136.1@2041.21,2096.7 ; C136.1@2041.3,2096.93 R145.1@2064.3,2096.93 ; R145.1@2064,2096.81 2065.8,2095.01 2065.8,2090.78 2078.96,2077.62 2085.4,2077.62 2087.2,2075.82 L7.1@2087.2,2075.03
NetC136_2: C136.2 L5.1 R143.2 R145.2 R155.2 | length 114.1
  Top Layer w9: R143.2@1997.3,2140.75 2018.1,2140.75 R155.2@2018.1,2139.97 2019.9,2138.17 2026.34,2138.17 2039.5,2125 2039.5,2120.78 C136.2@2041.3,2118.98 R145.2@2064.3,2118.98 ; R145.2@2064,2120.58 2065.8,2122.38 2065.8,2126.61 2078.96,2139.77 2085.4,2139.77 2087.2,2141.57 L5.1@2087.2,2142.36
NetC137_1: C137.1 L7.2 L8.1 | length 70.3
  Top Layer w9: L7.2@2113.26,2075.58 2113.26,2076.37 2115.06,2078.17 2121.5,2078.17 2134.66,2091.33 2134.66,2095.55 C137.1@2136.46,2097.35 ; C137.1@2136,2097.35 2137.8,2095.55 2137.8,2091.33 2150.96,2078.17 2157.4,2078.17 2159.2,2076.37 L8.1@2159.2,2075.58
NetC137_2: C137.2 L5.2 L6.1 | length 70.3
  Top Layer w9: L5.2@2113.26,2142.9 2113.26,2142.12 2115.06,2140.32 2121.5,2140.32 2134.66,2127.16 2134.66,2122.93 C137.2@2136.46,2121.13 ; C137.2@2136,2121.13 2137.8,2122.93 2137.8,2127.16 2150.96,2140.32 2157.4,2140.32 2159.2,2142.12 L6.1@2159.2,2142.9
NetC139_1: C139.1 R146.2 R147.2 | length 44
  Top Layer w9: R147.2@1659.83,2140.59 R146.2@1681.83,2140.59 C139.1@1703.83,2140.59
NetC139_2: C139.2 R148.1 | length 22.8
  Top Layer w9: C139.2@1725.88,2140.59 R148.1@1748.64,2140.59
NetC140_2: C140.2 R151.1 R152.2 R158.1 U21.2 | length 153.6
  Top Layer w9: R152.2@1869.25,2235.12 R152.2@1871.22,2235.12 ; U21.2@1884.25,2153.12 1884.25,2197.71 1899.25,2212.71 R151.1@1899.25,2235.12 R152.2@1871.22,2235.12 ; R158.1@1884.25,2265.12 1884.25,2250.12 1876.56,2242.43 1876.56,2240.46 R152.2@1871.22,2235.12
NetC141_1: C141.1 R156.1 U22.3 | length 91.3
  Top Layer w12: C141.1@2001.61,2366.3 2003.58,2366.3 2007.42,2362.45 2007.42,2360.49 2022.77,2345.14 2022.77,2328.17 2024.64,2326.3 U22.3@2025.23,2326.3 R156.1@2065.23,2326.3
NetC141_2: C141.2 R158.2 U22.4 | length 130.7
  Top Layer w9: R158.2@1884.25,2287.16 1884.25,2302.3 1908.24,2326.3 U22.4@1938.62,2326.3 1939.21,2326.3 1941.09,2328.17 1941.09,2345.14 1956.43,2360.49 1956.43,2362.45 1960.27,2366.3 C141.2@1962.24,2366.3
NetC142_1: C142.1 R154.1 R155.1 R156.2 | length 268
  Top Layer w12: R154.1@2018.02,2097.76 2018.1,2097.76 R155.1@2018.1,2117.92 ; v1(2087.28,2296.3) R156.2@2087.28,2326.3
  Bottom Layer w18: v1(2018.14,2107.2) 2018.14,2163.99 2055.41,2201.26 2055.41,2264.42 v1(2087.28,2296.3)
NetC153_1: C153.1 R159.2 R163.2 | length 44
  Top Layer w9: R159.2@1660.22,1074.57 R163.2@1682.22,1074.57 C153.1@1704.22,1074.57
NetC153_2: C153.2 R160.1 | length 22.6
  Top Layer w9: C153.2@1726.27,1074.57 1748.64,1074.57 R160.1@1748.64,1074.77
NetC155_1: C155.1 L11.1 R164.1 R169.2 R173.2 | length 114.3
  Top Layer w9: R169.2@1997,1074.93 2018.02,1074.93 2018.02,1075.71 2019.81,1077.51 2026.25,1077.51 2039.41,1090.68 2039.41,1094.9 C155.1@2041.21,1096.7 ; C155.1@2041.3,1096.93 R164.1@2064.3,1096.93 ; R164.1@2064,1096.81 2065.8,1095.01 2065.8,1090.78 2078.96,1077.62 2085.4,1077.62 2087.2,1075.82 L11.1@2087.2,1075.03
NetC155_2: C155.2 L9.1 R162.2 R164.2 R174.2 | length 114.1
  Top Layer w9: R162.2@1997.3,1140.75 2018.1,1140.75 2018.1,1139.97 2019.9,1138.17 2026.34,1138.17 2039.5,1125 2039.5,1120.78 2041.3,1118.98 R164.2@2064.3,1118.98 ; R164.2@2064,1120.58 2065.8,1122.38 2065.8,1126.61 2078.96,1139.77 2085.4,1139.77 2087.2,1141.57 L9.1@2087.2,1142.36
NetC156_1: C156.1 L11.2 L12.1 | length 70.3
  Top Layer w9: L11.2@2113.26,1075.58 2113.26,1076.37 2115.06,1078.17 2121.5,1078.17 2134.66,1091.33 2134.66,1095.55 C156.1@2136.46,1097.35 ; C156.1@2136,1097.35 2137.8,1095.55 2137.8,1091.33 2150.96,1078.17 2157.4,1078.17 2159.2,1076.37 L12.1@2159.2,1075.58
NetC156_2: C156.2 L9.2 L10.1 | length 70.3
  Top Layer w9: L9.2@2113.26,1142.9 2113.26,1142.12 2115.06,1140.32 2121.5,1140.32 2134.66,1127.16 2134.66,1122.93 C156.2@2136.46,1121.13 ; C156.2@2136,1121.13 2137.8,1122.93 2137.8,1127.16 2150.96,1140.32 2157.4,1140.32 2159.2,1142.12 L10.1@2159.2,1142.9
NetC158_1: C158.1 R167.1 | length 23
  Top Layer w9: C158.1@1726.27,1141.97 R167.1@1749.03,1141.97 R167.1@1749.03,1141.77
NetC158_2: C158.2 R165.1 R166.2 | length 44
  Top Layer w9: R166.2@1660.22,1141.97 R165.1@1682.22,1141.97 C158.2@1704.22,1141.97
NetC159_1: C159.1 R170.1 R171.2 R177.1 U23.2 | length 153.6
  Top Layer w9: R171.2@1869.25,1235.12 R171.2@1871.22,1235.12 ; U23.2@1884.25,1153.12 1884.25,1197.71 1899.25,1212.71 R170.1@1899.25,1235.12 R171.2@1871.22,1235.12 ; R177.1@1884.25,1265.12 1884.25,1250.12 1876.56,1242.43 1876.56,1240.46 R171.2@1871.22,1235.12
NetC160_1: C160.1 R175.1 U24.3 | length 91.3
  Top Layer w12: C160.1@2001.61,1366.3 2003.58,1366.3 2007.42,1362.45 2007.42,1360.49 2022.77,1345.14 2022.77,1328.17 2024.64,1326.3 U24.3@2025.23,1326.3 R175.1@2065.23,1326.3
NetC160_2: C160.2 R177.2 U24.4 | length 130.7
  Top Layer w9: R177.2@1884.25,1287.16 1884.25,1302.3 1908.24,1326.3 U24.4@1938.62,1326.3 1939.21,1326.3 1941.09,1328.17 1941.09,1345.14 1956.43,1360.49 1956.43,1362.45 1960.27,1366.3 C160.2@1962.24,1366.3
NetC161_1: C161.1 R173.1 R174.1 R175.2 | length 268.7
  Top Layer w9: R173.1@2018.1,1096.73 2018.14,1096.78 v1(2018.14,1107.2) 2018.14,1117.63 R174.1@2018.18,1117.68
  Top Layer w12: v1(2087.28,1296.3) R175.2@2087.28,1326.3
  Bottom Layer w18: v1(2018.14,1107.2) 2018.14,1171.8 2055.41,1209.07 2055.41,1264.42 v1(2087.28,1296.3)
NetC166_2: C166.2 C167.2 FB11.2 U28.9 | length 180.5
  Bottom Layer w8: U28.9@505.87,1467.41 U28.9@506.6,1468.14 534.21,1468.14 560.39,1441.96 C166.2@605.19,1441.96 C167.2@640.19,1441.96 FB11.2@675.19,1441.96
NetC174_2: C174.2 C175.2 FB12.2 U28.4 | length 225.4
  Bottom Layer w8: U28.4@506.6,1566.56 551.95,1566.56 594.32,1608.93 594.32,1655.42 C175.2@595.94,1657.04 595.94,1688.8 594.32,1690.42 C174.2@595.94,1692.04 FB12.2@595.94,1727.04
NetC181_2: C181.2 U28.2 Y1.1 | length 192.4
  Top Layer w8: Y1.1@372.69,1676.8 372.69,1627.14 390.9,1608.93 v1(459.75,1608.93)
  Bottom Layer w8: v1(459.75,1608.93) 476,1608.93 479,1605.93 U28.2@506.6,1605.93
NetC182_2: C182.2 U28.3 Y1.2 | length 192.4
  Top Layer w8: Y1.2@372.69,1515.38 372.69,1565.03 390.9,1583.25 v1(459.75,1583.25)
  Bottom Layer w8: v1(459.75,1583.25) 476,1583.25 479,1586.25 U28.3@506.6,1586.25
NetD1_2: D1.2 R3.2 | length 65.1
  Top Layer w5: D1.2@1398.9,541.25 1398.9,476.8 R3.2@1399.37,476.33
NetD2_2: D2.2 R1.1
  other v1: 940.1,498.46
NetD4_1: D4.1 F1.1 FB1.1 U2.6 U2.7 U2.8
NetD5_2: D5.2 R54.2
NetD7_1: D7.1 J10.A4 J10.B4 | length 705.5
  Top Layer w18: D7.1@208.37,2434.74 322.02,2434.74 357.32,2399.43 357.32,2318.01 336.24,2296.92 v1(309.46,2296.92) J10.A4@296.46,2296.92 v1(283.46,2296.92)
  Bottom Layer w18: v1(283.46,2107.95) v1(283.46,2296.92) ; v1(309.46,2107.95) v1(309.46,2296.92)
NetD7_2: D7.2 R225.2 | length 18.2
  Top Layer w9: v1(149.32,2434.74) D7.2@150.74,2433.32
  Bottom Layer w9: v1@149.15,2434.57 v1(149.32,2434.74) 149.67,2434.38 149.67,2419.38 R225.2@150.03,2419.03
NetF1_2: F1.2 R2.2 SW1.1 U2.3 U2.4 U2.5
NetF2_1: F2.1 J1.1 TP1.1
NetF2_3: F2.3 J1.2 J1.3 TP3.1
NetFB3_1: FB3.1 R20.1 U8.3 U9.8 | length 241.2
  Top Layer w9: R20.1@3650.39,432.35 v1(3650.39,452.04)
  Top Layer w18: R20.1@3650.39,432.35 v1(3650.39,452.04)
  Bottom Layer w8: v1(3600.39,432.35) 3600.39,383.17 3663.77,319.79 v1(3663.77,256.76)
NetFB4_1: FB4.1 R29.1 U10.3 U11.8 | length 241.2
  Top Layer w8: R29.1@3447.46,432.35 v1(3447.46,452.04)
  Top Layer w18: R29.1@3447.46,432.35 v1(3447.46,452.04)
  Bottom Layer w8: v1(3397.46,432.35) 3397.46,383.17 3460.84,319.79 v1(3460.84,256.76)
NetFB5_1: FB5.1 R37.1 U12.3 U13.8 | length 221.5
  Top Layer w18: R37.1@4071.7,432.35 v1(4071.7,452.04)
  Bottom Layer w8: v1(4021.7,432.35) 4021.7,383.17 4085.08,319.79 v1(4085.08,256.76)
